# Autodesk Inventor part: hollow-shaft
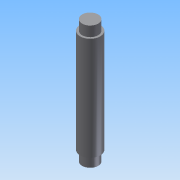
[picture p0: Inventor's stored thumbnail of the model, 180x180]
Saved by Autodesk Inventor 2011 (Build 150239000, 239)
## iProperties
Created: 2020-12
Part Number: hollow-shaft
Document SubType Name: Modeling
Designer: PC
Density: 1 g/cm^3
Author: PC
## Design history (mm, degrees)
sketch "Sketch1"
  geometry: C1 r 20 at (0, 0); 1 further point
  constraints: 1 centre point, 1 coincident
  dimensions: "d0" = 40 diameter of C1
extrude "Extrusion1" new body sketch "Sketch1" stored distance "d1" = 205.5; taper "d2" = 0 deg
shell "Shell1" dims "d3" = 4
sketch "Sketch2"
  geometry: C1 r 16 at (0, 0) reference
extrude "Extrusion2" join sketch "Sketch2" stored distance "d4" = 40; taper "d5" = 0 deg
mirror "Mirror1"
body "Solid1"
